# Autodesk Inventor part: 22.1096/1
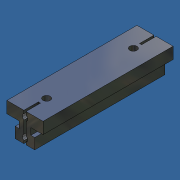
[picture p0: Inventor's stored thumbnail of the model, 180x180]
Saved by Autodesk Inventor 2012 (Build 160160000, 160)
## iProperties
Created: 2007-06
Part Number: 22.1096/1
Material: UHMW, Black
Document SubType Name: Modeling
Designer: Andy Moles
Density: 0.94 g/cm^3
Mass: 27.3772 g
Surface Area: 108.664 cm^2
Volume: 29.1247 cm^3
Description: L = 3.54", MACHINE TO 22.1096/1
Stock Number: 22.1088 SLIDE BAR 8
Author: Andy Moles
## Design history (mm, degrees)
sketch "Sketch1"
  geometry: L1 (4.1, 0)-(4.1, -4.6); L2 (12.5, 0)-(4.1, 0); L3 (12.5, 8)-(12.5, 0); L4 (-12.5, 8)-(12.5, 8); L5 (-12.5, 0)-(-12.5, 8); L6 (-4.1, 0)-(-12.5, 0); L7 (-4.1, -4.6)-(-4.1, 0); L8 (-6.75, -4.6)-(-4.1, -4.6); L9 (-6.75, -12)-(-6.75, -4.6); L10 (6.75, -12)-(-6.75, -12); L11 (6.75, -4.6)-(6.75, -12); L12 (4.1, -4.6)-(6.75, -4.6); 2 further points
  constraints: 24 end point
extrude "Extrusion1" new body sketch "Sketch1" stored distance "d0" = 90; taper "d1" = 0 deg
sketch "Sketch2"
  geometry: L1 (-12.5, 8)-(12.5, 8) reference; L2 (-12.5, 0)-(-12.5, 8) reference; L3 (-6.75, -12)-(-6.75, -4.6) reference; L4 (6.75, -12)-(-6.75, -12) reference; L5 (6.75, -4.6)-(6.75, -12) reference; L6 (-0.75, 8)-(0.75, 8); L7 (-0.75, -12)-(0.75, -12); L8 (-0.75, 5.854)-(-0.75, 8); L9 (0.75, 5.854)-(0.75, 8); L10 (-0.75, -12)-(-0.75, -10.154); L11 (-0.75, -6.446)-(-0.75, 2.146); L12 (0.75, -12)-(0.75, -10.154); L13 (0.75, -6.446)-(0.75, 2.146); A1 r 2 centre (0, 4) between (-0.75, 5.854) and (-0.75, 2.146); A2 r 2 centre (0, 4) between (0.75, 2.146) and (0.75, 5.854); A3 r 2 centre (0, -8.3) between (-0.75, -6.446) and (-0.75, -10.154); A4 r 2 centre (0, -8.3) between (0.75, -10.154) and (0.75, -6.446); 6 further points
  constraints: 16 end point, 8 point on circle, 6 perpendicular, 5 midpoint, 4 centre point, 4 parallel, 4 point on line, 3 vertical alignment, 2 horizontal alignment
extrude "Extrusion2" cut sketch "Sketch2" distance "d5" = 10; taper "d6" = 0 deg
sketch "Sketch3"
  geometry: C1 r 2.5 at (12.5, -75); 1 further point
  constraints: 1 centre point, 1 vertical alignment
  dimensions: "d7" = 5 diameter of C1; "d8" = 30 distance of C1.centre point (12.5, -45)
extrude "Extrusion3" cut sketch "Sketch3" distance "d9" = 10; taper "d10" = 0 deg
thread "Thread1" dims "d11" = 10, "d12" = 0
thread "Thread2" dims "d13" = 10, "d14" = 0
thread "Thread3" dims "d15" = 10, "d16" = 0
thread "Thread4" dims "d17" = 10, "d18" = 0
mirror "Mirror1"
body "Solid1"
other parameters: "d2" = 4, "d3" = 1.5, "d4" = 4
